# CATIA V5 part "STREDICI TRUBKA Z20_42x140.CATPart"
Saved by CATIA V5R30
Part number: STREDICI TRUBKA Z20/42x140
Bounding box of the stored display mesh (mm): x 0 to 140, y -20.99 to 20.99, z -21 to 21
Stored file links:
  C:\Users\ondra\Desktop\PŘÍLOHA P III\CATIA\STREDICI TRUBKA Z20_42x140.CATPart
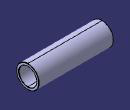
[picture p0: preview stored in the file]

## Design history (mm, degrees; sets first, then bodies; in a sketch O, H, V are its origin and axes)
Set1
  DatumSurface1 to DatumSurface18 "Z20/42x1"
  Join1: Elements (DatumSurface1; DatumSurface2; DatumSurface3; DatumSurface4; DatumSurface5; DatumSurface6; DatumSurface7; DatumSurface8; DatumSurface9; DatumSurface10; DatumSurface11; DatumSurface12; DatumSurface13; DatumSurface14; DatumSurface15; DatumSurface16; DatumSurface17; DatumSurface18)
Body1 (main body)
  CloseSurface1: CloseElement Join1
